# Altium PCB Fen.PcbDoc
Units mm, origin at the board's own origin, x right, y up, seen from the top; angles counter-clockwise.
Board outline 43.9 x 40 mm, 2 copper layers (Top Layer, Bottom Layer); 26 components, 24 nets, 91 pads, 0 vias.
Unrouted connection lines stored in the file: 1.
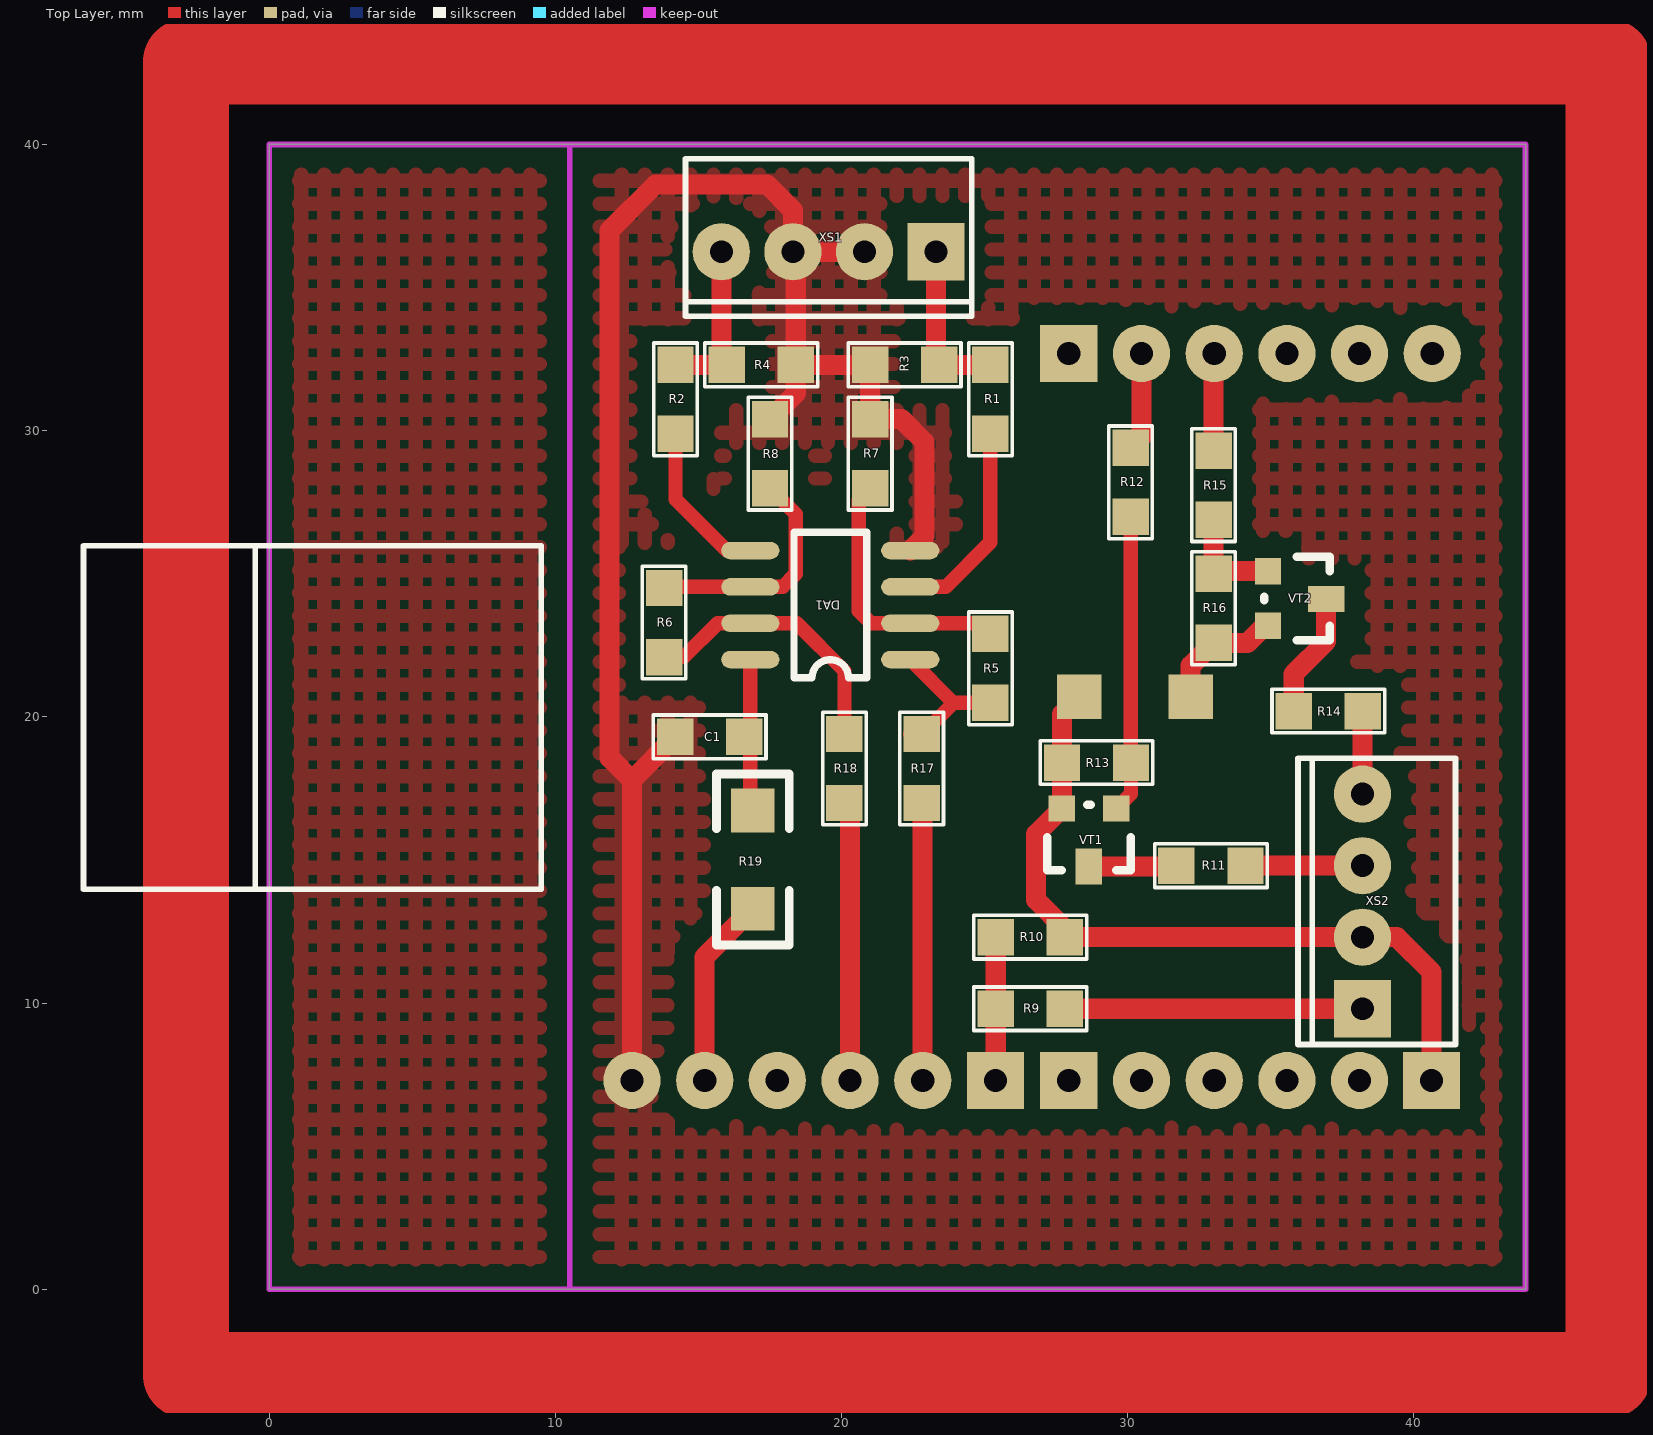
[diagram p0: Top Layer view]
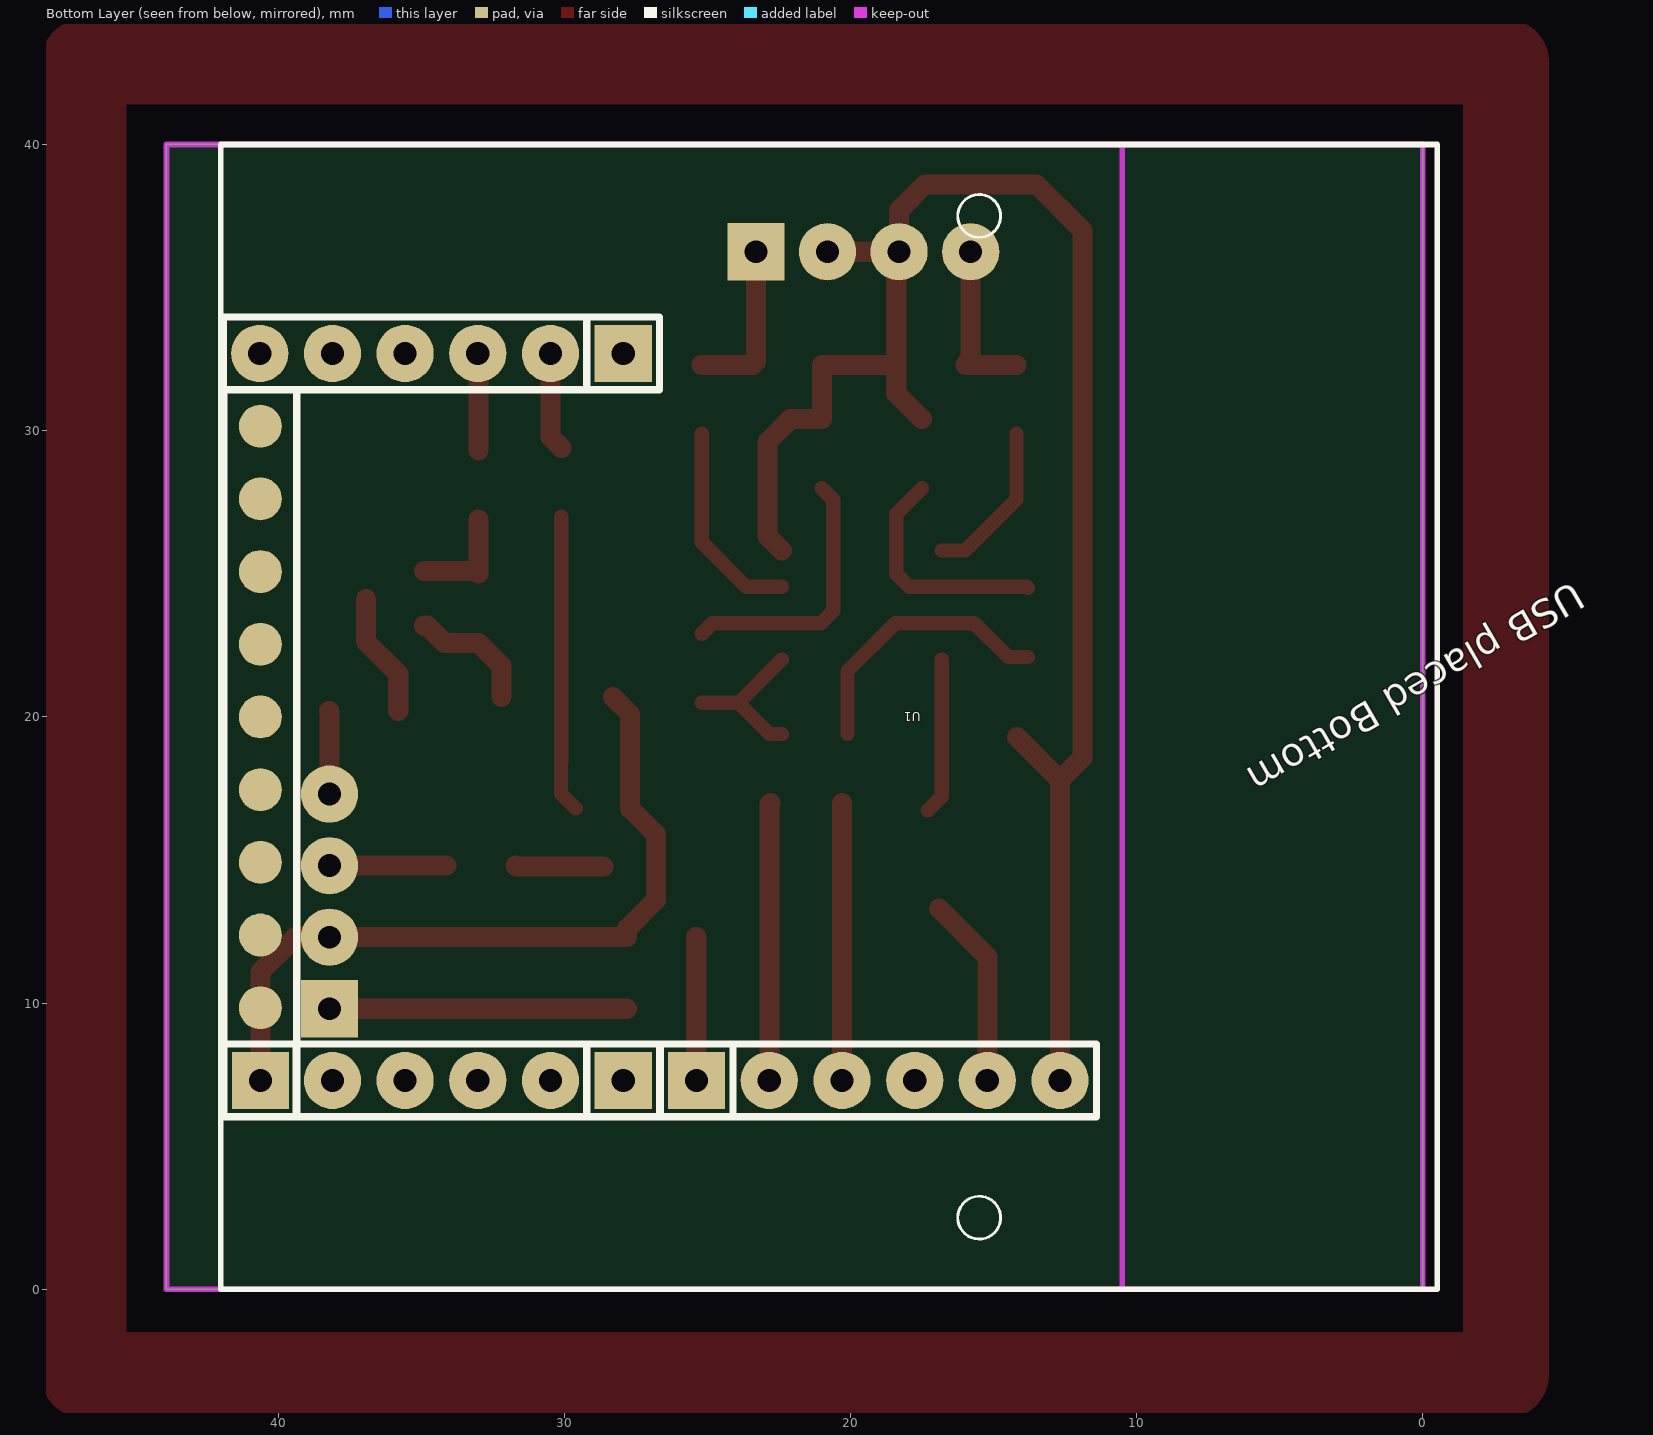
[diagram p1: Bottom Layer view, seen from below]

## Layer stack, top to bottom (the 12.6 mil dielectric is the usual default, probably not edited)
Top Solder: solder mask 0.0102, Solder Resist, Dk 3.5
Top Layer: signal copper 0.0356
Dielectric 1: dielectric 0.32, FR-4, Dk 4.8
Bottom Layer: signal copper 0.0356
Bottom Solder: solder mask 0.0102, Solder Resist, Dk 3.5

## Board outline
0,0 43.9,0 43.9,40 0,40

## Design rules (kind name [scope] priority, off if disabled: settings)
Clearance Clearance_1 [InNamedPolygon('TGND')] p1: gap=0.7
Clearance [All] p2: gap=0.254
ComponentClearance [All] p1 off: gap=0.254 collisioncheckmode=3 verticalgap=0.254 showdistances=FALSE
PolygonConnect [All] p1: connectstyle=Direct reliefconductorwidth=0.254 reliefentries=4 polygonreliefangle="90 Angle" airgapwidth=0.254
RoutingVias [All] p1: holewidth=0.5 width=0.7 viastyle="Through Hole" minholewidth=0.3 minwidth=0.5 maxholewidth=3 maxwidth=3
SolderMaskExpansion [All] p1: expansion=0.102
UnpouredPolygon [All] p1: allowunpoured=FALSE
Width [All] p1: maxlimit=20 minlimit=0.15 preferedwidth=0.5
28 further rules are at their usual default settings.

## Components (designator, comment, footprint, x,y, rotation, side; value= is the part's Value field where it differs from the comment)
C1 "100n" 0805 16.6,19.3 r180 top
DA1 "AD8602" SO-8 22.4,22 r180 top
R1 "1K" 0805 25.2,32.3 r270 top
R2 "1K" 0805 14.2,32.3 r270 top
R3 "10K" 0805 21,32.3 r0 top
R4 "10K" 0805 18.4,32.3 r180 top
R5 "100K" 0805 25.2,22.9 r270 top
R6 "100K" 0805 13.8,24.5 r270 top
R7 "1K" 0805 21,30.4 r270 top
R8 "1K" 0805 17.5,30.4 r270 top
R9 "20K" 0805 27.8,9.8 r180 top
R10 "20K" 0805 27.8,12.3 r180 top
R11 "1K" 0805 31.7,14.8 r0 top
R12 "10K" 0805 30.1,29.4 r270 top
R13 "47K" 0805 27.7,18.4 r0 top
R14 "10R" 0805 35.8,20.2 r0 top
R15 "10K" 0805 33,29.3 r270 top
R16 "47K" 0805 33,22.587 r90 top
R17 "160K" 0805 22.8,19.4 r270 top
R18 "160K" 0805 20.1,19.4 r270 top
R19 "0.47R" 1206 16.9,13.3 r90 top
U1 "USB_CONTROL" F_FTDI_CONTROL -0.5,40 r0 bottom locked
VT1 "BC817" SOT-23 29.6,16.8 r180 top
VT2 "BC817" SOT-23 34.9,25.087 r270 top
XS1 "Sensors" F_OWF-4 23.3,36.25 r180 top
XS2 "Boards" F_OWF-4 38.2,9.8 r90 top

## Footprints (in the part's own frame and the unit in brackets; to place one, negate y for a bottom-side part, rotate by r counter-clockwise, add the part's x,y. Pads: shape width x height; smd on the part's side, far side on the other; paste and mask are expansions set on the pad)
0805 [mil]
  rect 50x50 smd: 1(0,0) 2(95,0)
  silkscreen extent -30,-30 125,30
1206 [mil]
  rect 60x60 smd: 1(0,0) 2(135,0)
  silkscreen extent -50,-50 185,50
F_FTDI_CONTROL [mm]
  rect 2x2 hole 0.813: 1(28.44,7.304) 16(41.116,32.704) 21(28.44,32.704) 22(25.876,32.704)
  round 2 hole 0.813: 2(30.98,7.304) 3(33.52,7.304) 4(36.06,7.304) 5(38.6,7.304) 6(41.14,7.304) 17(38.6,32.704) 18(36.06,32.704) 19(33.52,32.704) 20(30.98,32.704) 23(23.336,32.704) 24(20.796,32.704) 25(18.256,32.704) 26(15.716,32.704) 27(13.176,32.704)
  round 1.5 smd: 7(41.116,9.844) 8(41.116,12.384) 9(41.116,14.924) 10(41.116,17.464) 11(41.116,20.004) 12(41.116,22.544) 13(41.116,25.084) 14(41.116,27.624) 15(41.116,30.164)
  silkscreen extent 0,0 42.5,40
F_OWF-4 [mm] "OWF-4 вилка на плату 2.50мм прям. откр."
  rect 2x2 hole 0.8 mask+0: 1(0,0)
  round 2 hole 0.8 mask+0: 2(2.5,0) 3(5,0) 4(7.5,0)
  silkscreen extent -1.25,-3.25 8.75,2.25
SO-8 [mil]
  oval 80x24 smd: 1(0,0) 2(0,-50) 3(0,-100) 4(0,-150) 5(220,-150) 6(220,-100) 7(220,-50) 8(220,0)
  silkscreen extent 60,-175 160,25
SOT-23 [mil]
  rect 36x36 smd: 1(0,0) 2(75,0)
  rect 36x50 smd: 3(38,80)
  silkscreen extent -20,-5 95,85

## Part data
C1: library part C
DA1: library part LM393, "Сдвоенный компаратор"
R1 R2 R3 R4 R5 R6 R7 R8 R9 R10 R11 R12 R13 R14 R15 R16 R17 R18 R19: library part R
U1: "PIC с FTDI232"
XS1 XS2: library part CONN_4, "ТЕЛЕВИЗИОННЫЙ РАЗЪЕМ"

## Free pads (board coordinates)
  rect 1.55x1.55 smd: 0(28.3,20.7) 1(32.2,20.7)

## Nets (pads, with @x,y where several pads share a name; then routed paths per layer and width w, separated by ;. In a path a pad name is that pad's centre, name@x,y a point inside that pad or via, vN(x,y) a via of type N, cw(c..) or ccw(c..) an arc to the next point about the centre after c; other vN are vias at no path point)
+5VA: R19.1 U1.26 | length 6.7
  Top Layer w0.7: U1.26 15.216,11.616 R19.1
DGND: pad.0 pad.1 R10.1 R13.1 R16.1 U1.16 VT1.2 VT2.2 XS2.2 | length 30.9
  Top Layer w0.7: pad.0 27.7,20.1 R13.1 27.7,16.805 VT1.2 26.8,15.905 26.8,13.6 27.8,12.6 R10.1 XS2.2 39.4,12.3 40.616,11.084 U1.16 ; pad.1 32.2,21.787 R16.1 34.187,22.587 34.782,23.182 VT2.2
GND: C1.2 DA1.4 R3.1 R4.1 R7.1 R8.1 U1.27 XS1.2 XS1.3 | length 60.5
  Top Layer w0.7: U1.27 12.676,17.789 ; C1.2 12.676,17.789 ; R8.1 18.4,31.3 R4.1 ; XS1.2 XS1.3 ; DA1.4 22.9,26.31 22.9,29.6 22.1,30.4 R7.1 R3.1 R4.1 ; 12.676,17.789 11.9,18.565 11.9,37 13.5,38.6 17.4,38.6 18.3,37.7 XS1.3 ; XS1.3 18.4,36.15 R4.1
NetC1_1: C1.1 DA1.8 R19.2 | length 5.5
  Top Layer w0.5: DA1.8 16.812,17.217 R19.2@17.3,16.729
NetDA1_1: DA1.1 R5.2 R17.1 | length 5.4
  Top Layer w0.5: R17.1@22.4,19.4 22.826,19.4 23.913,20.487 ; DA1.1 23.913,20.487 ; R5.2 23.913,20.487
NetDA1_2: DA1.2 R5.1 R7.2 | length 9.4
  Top Layer w0.5: R7.2 20.6,27.587 20.6,23.7 21.03,23.27 DA1.2 24.83,23.27 R5.1
NetDA1_3: DA1.3 R1.2 | length 7.2
  Top Layer w0.5: DA1.3 23.64,24.54 25.2,26.1 R1.2
NetDA1_5: DA1.5 R2.2 | length 5.6
  Top Layer w0.5: R2.2 14.2,27.6 15.99,25.81 DA1.5
NetDA1_6: DA1.6 R6.1 R8.2 | length 8.2
  Top Layer w0.5: R6.1 13.84,24.54 DA1.6 17.94,24.54 18.4,25 18.4,27.087 R8.2
NetDA1_7: DA1.7 R6.2 R18.1 | length 9.7
  Top Layer w0.5: R6.2 14.487,22.087 15.67,23.27 DA1.7 18.43,23.27 20.1,21.6 R18.1
NetR11_1: R11.1 VT1.3 | length 3.1
  Top Layer w0.7: VT1.3 31.668,14.768 R11.1
NetR12_2: R12.2 R13.2 VT1.1 | length 10.4
  Top Layer w0.5: VT1.1 30.113,17.313 R13.2 30.1,18.413 R12.2
NetR14_1: R14.1 VT2.3 | length 4.4
  Top Layer w0.7: R14.1 35.8,21.5 36.932,22.632 VT2.3
NetR15_2: R15.2 R16.2 VT2.1 | length 3.8
  Top Layer w0.7: R15.2 R16.2 33.087,25.087 VT2.1
ONOFF: R14.2 XS2.4 | length 2.9
  Top Layer w0.7: XS2.4 38.2,20.187 R14.2
P_ONOFF: R15.1 U1.3 | length 3.4
  Top Layer w0.7: R15.1 33,32.676 U1.3
P_S0: R9.2 R10.2 U1.22 | length 5
  Top Layer w0.7: U1.22 25.387,7.307 R9.2 R10.2
P_S1: R17.2 U1.23 | length 9.7
  Top Layer w0.7: R17.2 22.836,16.951 U1.23
P_S2: R18.2 U1.24 | length 9.7
  Top Layer w0.7: U1.24 R18.2@20.296,16.987
P_TCON: R12.1 U1.2 | length 3.5
  Top Layer w0.7: R12.1 30.48,29.78 U1.2
S0: R9.1 XS2.1 | length 10.4
  Top Layer w0.7: R9.1 XS2.1
S1: R1.1 R3.2 XS1.1 | length 5.8
  Top Layer w0.7: XS1.1 23.3,32.413 R3.2 R1.1
S2: R2.1 R4.2 XS1.4 | length 5.8
  Top Layer w0.7: R2.1 R4.2 15.8,32.487 XS1.4
T_CON: R11.2 XS2.3 | length 4.1
  Top Layer w0.7: R11.2 XS2.3
pads on no net: U1.1 U1.4 U1.5 U1.6 U1.7 U1.8 U1.9 U1.10 U1.11 U1.12 U1.13 U1.14 U1.15 U1.17 U1.18 U1.19 U1.20 U1.21 U1.25
copper on no net: | length 191.2
  Top Layer w3: -2.9,-3 46.8,-3 46.8,42 46.8,42.9 -2.9,42.9 -2.9,-3

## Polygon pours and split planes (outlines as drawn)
GND on Top Layer "TGND" (hatched 90Degree grid 0.8 track 0.5, pour order 3): 0,0 10.5,0 10.5,40 0,40 0,0
GND on Top Layer "TGND" (hatched 90Degree grid 0.8 track 0.5, remove dead copper, pour order 2): 10.5,0 43.9,0 43.9,40 10.5,40 10.5,0

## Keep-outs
Keep-Out Layer:
  lines w0.2: 10.5,0 0,0 0,40 10.5,40 ; 10.5,0 10.5,40 ; 10.5,0 43.9,0 43.9,40 10.5,40

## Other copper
Top Layer:
  pour cut-out: 15.3,18.4 15.3,12.6 15.8,12.6 15.9,12.7 15.9,18.4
